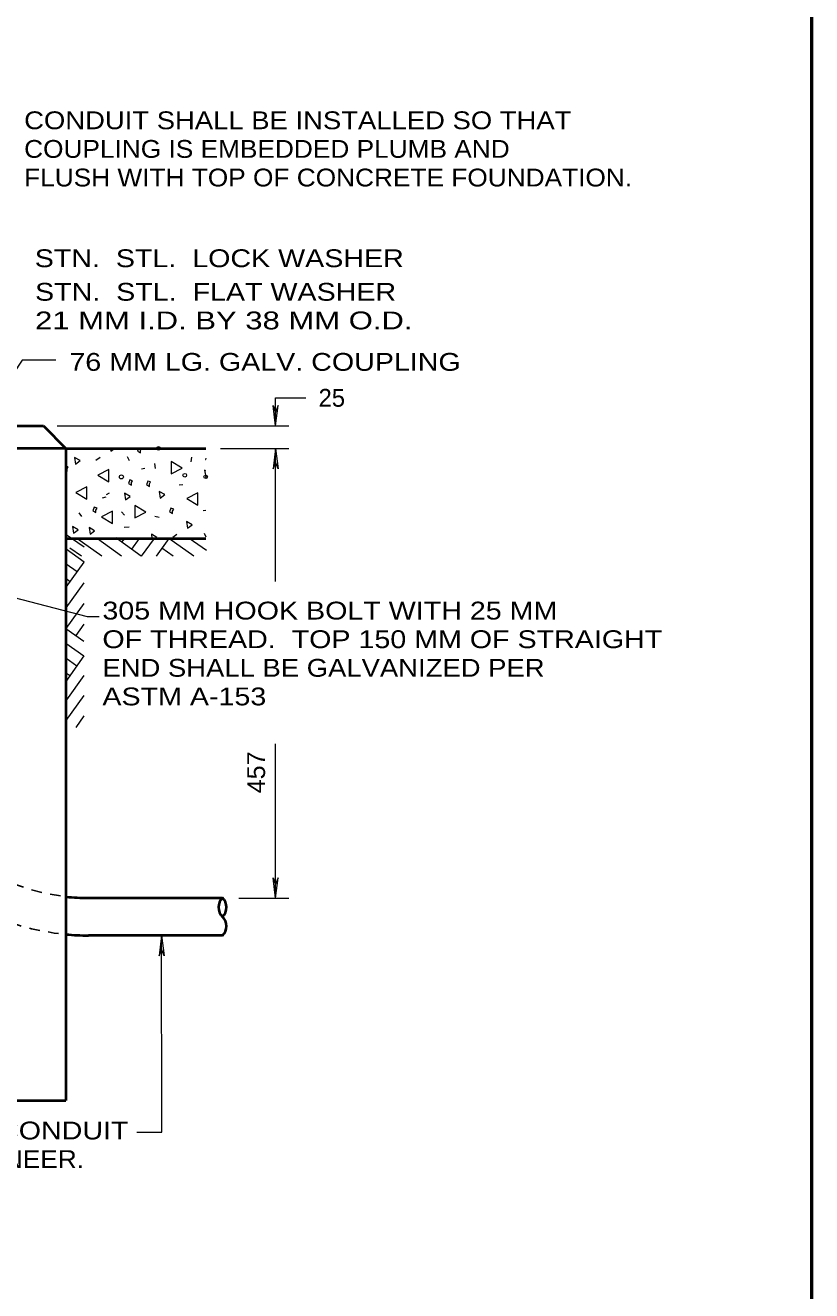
# Model space of a CAD drawing. Extents: x 312583 to 312854, y 144419 to 144597.
# Drawn here: x 312720.8 to 312754.3, y 144472.5 to 144526.5 of the extents above; entities that cross this region are included whole.
import ezdxf

# ---------------------------------------------------------------- set-up
doc = ezdxf.new("R2010")
doc.units = 0
doc.header["$LTSCALE"] = 0.3
doc.header["$PDMODE"] = 32
doc.header["$PDSIZE"] = 0.15
doc.linetypes.add('SHORT_DASHED', pattern=[2.7, 1.5, -1.2])
doc.layers.add('1', color=7, linetype='Continuous', lineweight=25)
doc.layers.add('2', color=7, linetype='Continuous', lineweight=13)

msp = doc.modelspace()

# ---------------------------------------------------------------- linework, layer by layer
at = {"layer": '1', "lineweight": 53}
msp.add_line((312754.2862, 144423.0846), (312754.2862, 144585.0846), dxfattribs=at)
at = {"layer": '1', "lineweight": 40}
for p, q in [((312706.2239, 144509.3872), (312721.5572, 144509.3872)), ((312721.5572, 144509.3872), (312722.5155, 144508.4289)), ((312722.5155, 144508.4289), (312719.1422, 144508.4289)), ((312722.5155, 144508.4289), (312722.5155, 144480.6372)), ((312722.5155, 144508.4289), (312728.4725, 144508.4289)), ((312722.5155, 144504.5955), (312728.4725, 144504.5955)), ((312729.1855, 144489.2622), (312723.4739, 144489.2622)), ((312729.1855, 144487.6675), (312723.4739, 144487.6675)), ((312705.2655, 144480.6372), (312722.5155, 144480.6372))]:
    msp.add_line(p, q, dxfattribs=at)
at = {"layer": '1', "linetype": 'SHORT_DASHED'}
for radius, end in [(10.3816, 264.70346), (8.785, 263.73732)]:
    msp.add_arc((312723.4767, 144498.0511), radius, 180, end, dxfattribs=at)
at = {"layer": '1', "lineweight": 40}
for centre, radius, start, end in [((312723.4767, 144498.0511), 8.785, 263.73732, 270), ((312729.5582, 144488.8669), 0.5448, 132.89064, 227.10937), ((312728.8167, 144488.8669), 0.5448, 312.89063, 47.10936), ((312728.8167, 144488.0686), 0.5448, 312.89063, 47.10936), ((312723.4767, 144498.0511), 10.3816, 264.70346, 270)]:
    msp.add_arc(centre, radius, start, end, dxfattribs=at)
at = {"layer": '2'}
for p, q in [((312731.3399, 144510.2535), (312731.4472, 144509.9775)), ((312731.4472, 144509.3872), (312731.3399, 144510.2535)), ((312731.4472, 144509.3872), (312731.4472, 144510.5832)), ((312731.4472, 144510.5832), (312732.7352, 144510.5832)), ((312731.5545, 144510.2535), (312731.4472, 144509.9775)), ((312731.4472, 144509.3872), (312731.5545, 144510.2535)), ((312722.1475, 144509.3872), (312732.0145, 144509.3872)), ((312723.9799, 144508.0379), (312723.7959, 144507.9075)), ((312724.4092, 144508.4289), (312724.4245, 144508.3062)), ((312724.4245, 144508.3062), (312724.5932, 144508.4289)), ((312725.1299, 144508.0839), (312725.2142, 144507.9152)), ((312727.1615, 144508.4289), (312727.1692, 144508.3905)), ((312727.1692, 144508.3905), (312727.2229, 144508.4289)), ((312727.8592, 144507.8615), (312727.8822, 144508.0532)), ((312729.1012, 144508.4289), (312732.0145, 144508.4289)), ((312731.4472, 144508.4289), (312731.3399, 144507.5625)), ((312731.4472, 144508.4289), (312731.5545, 144507.5625)), ((312731.4472, 144502.7555), (312731.4472, 144508.4289)), ((312725.7355, 144507.5549), (312725.8812, 144507.5932)), ((312726.2952, 144507.7849), (312726.3182, 144507.5779)), ((312731.3399, 144507.5625), (312731.4472, 144507.8385)), ((312731.5545, 144507.5625), (312731.4472, 144507.8385)), ((312727.3455, 144506.8802), (312727.4912, 144506.8879)), ((312724.0795, 144506.3282), (312724.2252, 144506.3589)), ((312724.2482, 144506.4585), (312724.3709, 144506.5352)), ((312723.0675, 144505.6765), (312723.1749, 144505.5309)), ((312724.8845, 144505.7302), (312725.0072, 144505.5769)), ((312726.3105, 144505.5385), (312726.4869, 144505.5002)), ((312728.3575, 144505.7839), (312728.4725, 144505.7915)), ((312722.5309, 144504.7642), (312723.2899, 144504.2275)), ((312724.9995, 144505.0785), (312725.2142, 144505.0862)), ((312727.2459, 144504.7642), (312727.0695, 144504.6339)), ((312728.4035, 144504.8102), (312728.4725, 144504.6645)), ((312723.1749, 144503.8365), (312722.6842, 144504.1815)), ((312724.0489, 144503.8365), (312722.9832, 144504.5955)), ((312724.8922, 144503.8365), (312723.8572, 144504.5802)), ((312725.7279, 144503.8365), (312724.6392, 144504.6109)), ((312725.0149, 144504.5955), (312724.8922, 144504.4269)), ((312725.6435, 144504.5955), (312725.3139, 144504.1355)), ((312726.2722, 144504.5955), (312725.7279, 144503.8365)), ((312726.9009, 144504.5955), (312726.3565, 144503.8365)), ((312727.0849, 144503.8365), (312726.6019, 144504.1815)), ((312727.9665, 144503.8365), (312726.9009, 144504.5955)), ((312728.5109, 144504.0742), (312727.7749, 144504.5955)), ((312722.5309, 144504.1432), (312723.2899, 144503.5989)), ((312723.2822, 144503.5835), (312722.5155, 144502.5102)), ((312722.5309, 144503.5145), (312722.9985, 144503.1849)), ((312723.2822, 144502.7019), (312722.5155, 144501.6285)), ((312722.5309, 144502.8859), (312722.6995, 144502.7632)), ((312723.2822, 144501.8202), (312722.5155, 144500.7545)), ((312722.5155, 144500.7545), (312723.2822, 144500.2102)), ((312723.2822, 144500.9385), (312722.9372, 144500.4555)), ((312722.5155, 144500.1259), (312723.2822, 144499.5815)), ((312723.2822, 144499.5815), (312722.5079, 144498.4929)), ((312722.5155, 144499.4972), (312722.9832, 144499.1675)), ((312722.5155, 144498.8685), (312722.6919, 144498.7459)), ((312723.2822, 144498.7459), (312722.5385, 144497.7109)), ((312723.2822, 144497.9025), (312722.5155, 144496.8369)), ((312723.2822, 144497.0285), (312722.9372, 144496.5379)), ((312731.4472, 144489.2622), (312731.4472, 144495.8325)), ((312731.3399, 144490.1285), (312731.4472, 144489.8525)), ((312731.4472, 144489.2622), (312731.3399, 144490.1285)), ((312731.5545, 144490.1285), (312731.4472, 144489.8525)), ((312731.4472, 144489.2622), (312731.5545, 144490.1285)), ((312729.8832, 144489.2622), (312732.0145, 144489.2622)), ((312726.5942, 144487.6675), (312726.4869, 144486.8012)), ((312726.5942, 144487.6675), (312726.7015, 144486.8012)), ((312726.4869, 144486.8012), (312726.5942, 144487.0772)), ((312726.7015, 144486.8012), (312726.5942, 144487.0772))]:
    msp.add_line(p, q, dxfattribs=at)
for points in [[(312722.0885, 144512.1932), (312720.6602, 144512.1932), (312718.0459, 144508.2449)], [(312725.6129, 144508.4289), (312725.5669, 144508.3062), (312725.6972, 144508.2372), (312725.6972, 144508.3445)], [(312725.6972, 144508.3445), (312725.7432, 144508.4289), (312725.7202, 144508.4289)], [(312728.4725, 144508.0072), (312728.4572, 144507.9612), (312728.4725, 144507.9535)], [(312722.5692, 144507.5549), (312722.6152, 144507.6392), (312722.5232, 144507.6699)], [(312722.5232, 144507.4782), (312722.5692, 144507.4475), (312722.5692, 144507.5549)], [(312728.4725, 144507.4782), (312728.4265, 144507.5012), (312728.4725, 144507.2175)], [(312726.3489, 144504.6032), (312726.3872, 144504.6339), (312726.1572, 144504.7719), (312726.1802, 144504.5955)], [(312723.9338, 144501.2529), (312723.4437, 144501.2529), (312717.8542, 144502.7019)], [(312725.5362, 144479.2802), (312726.6019, 144479.2802), (312726.5942, 144487.6675)]]:
    msp.add_lwpolyline(points, dxfattribs=at)
for points in [[(312722.9219, 144507.7619), (312723.1212, 144507.9075), (312722.8835, 144508.0455)], [(312724.3479, 144507.0029), (312724.3479, 144507.5242), (312723.8802, 144507.2865)], [(312727.0082, 144507.8692), (312727.0082, 144507.3479), (312727.4759, 144507.5855)], [(312725.3139, 144506.9722), (312725.3599, 144507.0489), (312725.2449, 144507.0872), (312725.1835, 144506.9339), (312725.3139, 144506.8649)], [(312726.0805, 144506.9185), (312726.1265, 144507.0029), (312726.0115, 144507.0335), (312725.9502, 144506.8802), (312726.0805, 144506.8112)], [(312723.4049, 144506.2669), (312723.4049, 144506.7882), (312722.9372, 144506.5505)], [(312725.0609, 144506.2362), (312725.2525, 144506.3819), (312725.0149, 144506.5199)], [(312726.5329, 144506.3129), (312726.7322, 144506.4585), (312726.4945, 144506.5965)], [(312728.1429, 144506.0139), (312728.1429, 144506.5352), (312727.6752, 144506.2975)], [(312723.7959, 144505.7992), (312723.8419, 144505.8835), (312723.7269, 144505.9219), (312723.6655, 144505.7685), (312723.7959, 144505.6995)], [(312725.4519, 144505.9909), (312725.4519, 144505.4772), (312725.9195, 144505.7072)], [(312727.0619, 144505.7609), (312727.1079, 144505.8452), (312726.9929, 144505.8759), (312726.9315, 144505.7225), (312727.0619, 144505.6535)], [(312724.5012, 144505.2319), (312724.5012, 144505.7532), (312724.0335, 144505.5155)], [(312727.6982, 144505.0325), (312727.8899, 144505.1782), (312727.6599, 144505.3162)], [(312722.8452, 144504.8102), (312723.0369, 144504.9635), (312722.7992, 144505.1015)], [(312723.5505, 144504.7719), (312723.7422, 144504.9175), (312723.5122, 144505.0555)]]:
    msp.add_lwpolyline(points, close=True, dxfattribs=at)
for centre, radius in [((312724.8818, 144507.216), 0.0865), ((312727.582, 144507.2862), 0.0784)]:
    msp.add_circle(centre, radius, dxfattribs=at)
for p in [(312726.4639, 144508.4289), (312728.4725, 144507.2175)]:
    msp.add_point(p, dxfattribs=at)

# ---------------------------------------------------------------- texts
for s, width, p in [('CONDUIT SHALL BE INSTALLED SO THAT', 1.15, (312720.7371, 144522.0362)), ('COUPLING IS EMBEDDED PLUMB AND', 1.1, (312720.7371, 144520.8162)), ('FLUSH WITH TOP OF CONCRETE FOUNDATION.', 1.1, (312720.7371, 144519.5962)), ('STN.  STL.  LOCK WASHER', 1.2, (312721.1892, 144516.1559)), ('STN.  STL.  FLAT WASHER', 1.2, (312721.2025, 144514.7245)), ('21 MM I.D. BY 38 MM O.D.', 1.3, (312721.2025, 144513.5045)), ('76 MM LG. GALV. COUPLING', 1.2, (312722.6648, 144511.738)), ('305 MM HOOK BOLT WITH 25 MM', 1.2, (312724.0716, 144501.1359)), ('OF THREAD.  TOP 150 MM OF STRAIGHT', 1.2, (312724.0716, 144499.9159)), ('END SHALL BE GALVANIZED PER', 1.15, (312724.0716, 144498.6959)), ('ASTM A-153', 1.2, (312724.0716, 144497.4759)), ('INSTALL TEE DRAINS IN CONDUIT', 1.2, (312705.1252, 144478.9729)), ("RUN WHEN REQ'D BY ENGINEER.", 1.1, (312705.1252, 144477.7529))]:
    msp.add_text(s, height=0.76, dxfattribs=dict(at, width=width)).set_placement(p)
msp.add_text('25', height=0.76, dxfattribs=at).set_placement((312733.2789, 144510.2063))
at = {"layer": '2', "width": 1.05}
msp.add_text('457', height=0.76, rotation=90, dxfattribs=at).set_placement((312731.001, 144493.7286))

doc.saveas('drawing.dxf')
